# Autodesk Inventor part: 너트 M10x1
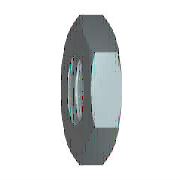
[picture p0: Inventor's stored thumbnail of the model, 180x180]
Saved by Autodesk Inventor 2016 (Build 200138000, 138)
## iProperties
Created: 2012-02
Part Number: 너트 M10x1
Material: 강철, 연강
Description: 6각 가는 너트 - 이중 모따기(부품 등급 A) - 정밀 나사산
Document SubType Name: Modeling
Standard: JIS B 1181
Designer: mduedu
Standards Organization: JIS
Language: ko-KR
Size Designation: M10x1
Categories: <MemberInstance><Categories><Category DisplayName="조임쇠" InternalName="e4da775c-781d-43d5-af7c-5136215cf5a6" Mnemonic="FSTN"><Category DisplayName="너트" InternalN
Density: 7.86 g/cm^3
Appearance: 강철
IsCustomPart: 1
Author: mduedu
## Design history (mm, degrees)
node "MSC_A1"
node "MSC_PT1"
node "MSC_PT2"
node "MSC_PF1"
body "Solid1"
sketch "스케치1"
  geometry: L1 (8, 4.619)-(8, -4.619); L2 (8, -4.619)-(0, -9.238); L3 (0, -9.238)-(-8, -4.619); L4 (-8, -4.619)-(-8, 4.619); L5 (-8, 4.619)-(0, 9.238); L6 (0, 9.238)-(8, 4.619); C1 r 8 at (0, 0); 2 further points
  constraints: 12 end point, 2 coincident, 1 centre point, 1 tangent, 1 vertical, 11 other
  dimensions: "d0" = 16 diameter of C1 (= ParS)
extrude "돌출1" new body sketch "스케치1" distance "d1" = 5 (= M); taper "d2" = 0 deg
sketch "스케치2"
  geometry: L1 (-8, 4.619)-(0, 9.238) reference; L2 (0, -9.238)-(-8, -4.619) reference; L3 (-8, 4.619)-(8, -4.619); L4 (-8, -4.619)-(8, 4.619); 1 further point
  constraints: 4 end point, 2 midpoint, 2 parallel
hole "구멍1" sketch "스케치2" diameter "d3" = 8.91747; stored, may be unused: countersink angle "d7" = 90 deg, drill point angle "d9" = 118 deg; dims "d4" = 6, "d5" = 4, "d6" = 2, "d8" = 8
chamfer "모따기1" distance "d10" = 0.5 (= 0.5 x PTC); stored, may be unused: second distance "d11" = 2, angle "d12" = 45 deg
revolve "회전1" stored, may be unused: angle "d15" = 90 deg
sketch "스케치3"
  geometry: L1 (-9.238, 5)-(-9.238, 4.285); L2 (-9.238, 4.285)-(-8, 5); L3 (-8, 5)-(-9.238, 5); L4 (-9.238, 0.715)-(-9.238, 0); L5 (-9.238, 0)-(-8, 0); L6 (-8, 0)-(-9.238, 0.715); L7 (0, 6)-(0, -1) reference; L8 (-4.619, 5)-(-9.238, 5) reference; L9 (-4.619, 0)-(-9.238, 0) reference; L10 (-9.238, 0)-(-9.238, 5) reference
  constraints: 12 end point, 4 collinear, 3 perpendicular, 2 equal length, 1 vertical
  dimensions: "d13" = 30 deg angle of L2 L3; "d14" = 8 distance from line of L2.end L7 (= 0.5 x ParS)
other parameters: "ParS" = 16 [user parameter; used in 2 equation terms], "M" = 5 [user parameter; used in 1 equation term], "PTC" = 1 [user parameter; used in 1 equation term], "d17" = 0, "d18" = 0, "d19" = 0, "d20" = 0, "d21" = 0, "d22" = 0, "d23" = 0
